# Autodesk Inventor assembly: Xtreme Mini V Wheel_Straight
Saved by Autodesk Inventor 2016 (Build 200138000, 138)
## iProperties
Created: 2016-03
Part Number: Xtreme Mini V Wheel_Straight
Document SubType Name: Assembly
Designer: bongo_000
Author: bongo_000
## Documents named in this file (6)
- C:\Users\bongo_000\Downloads\DLP\Xtreme Mini V Wheel_Straight.iam
- C:\Users\bongo_000\Downloads\DLP\Ball Bearing 5 x 10 x 4.2.ipt
- C:\Users\bongo_000\Downloads\DLP\Precision Shim 8 x 5 x 1.ipt
- C:\Users\bongo_000\Downloads\DLP\Xtreme Mini V Wheel.ipt
- C:\Users\bongo_000\Downloads\DLP\Aluminum Spacer 6mm.ipt
- C:\Users\bongo_000\Downloads\DLP\Nylon Insert Lock Nut M5.ipt
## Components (7 placed, 7 different names)
1. Ball Bearing 5 x 10 x 4.2_1007
2. Precision Shim 8 x 5 x 1_1008
3. Xtreme Mini V Wheel_1009
4. Precision Shim 8 x 5 x 1_1010
5. Aluminum Spacer 6mm_1011
6. Ball Bearing 5 x 10 x 4.2_1012
7. Nylon Insert Lock Nut M5_1013
